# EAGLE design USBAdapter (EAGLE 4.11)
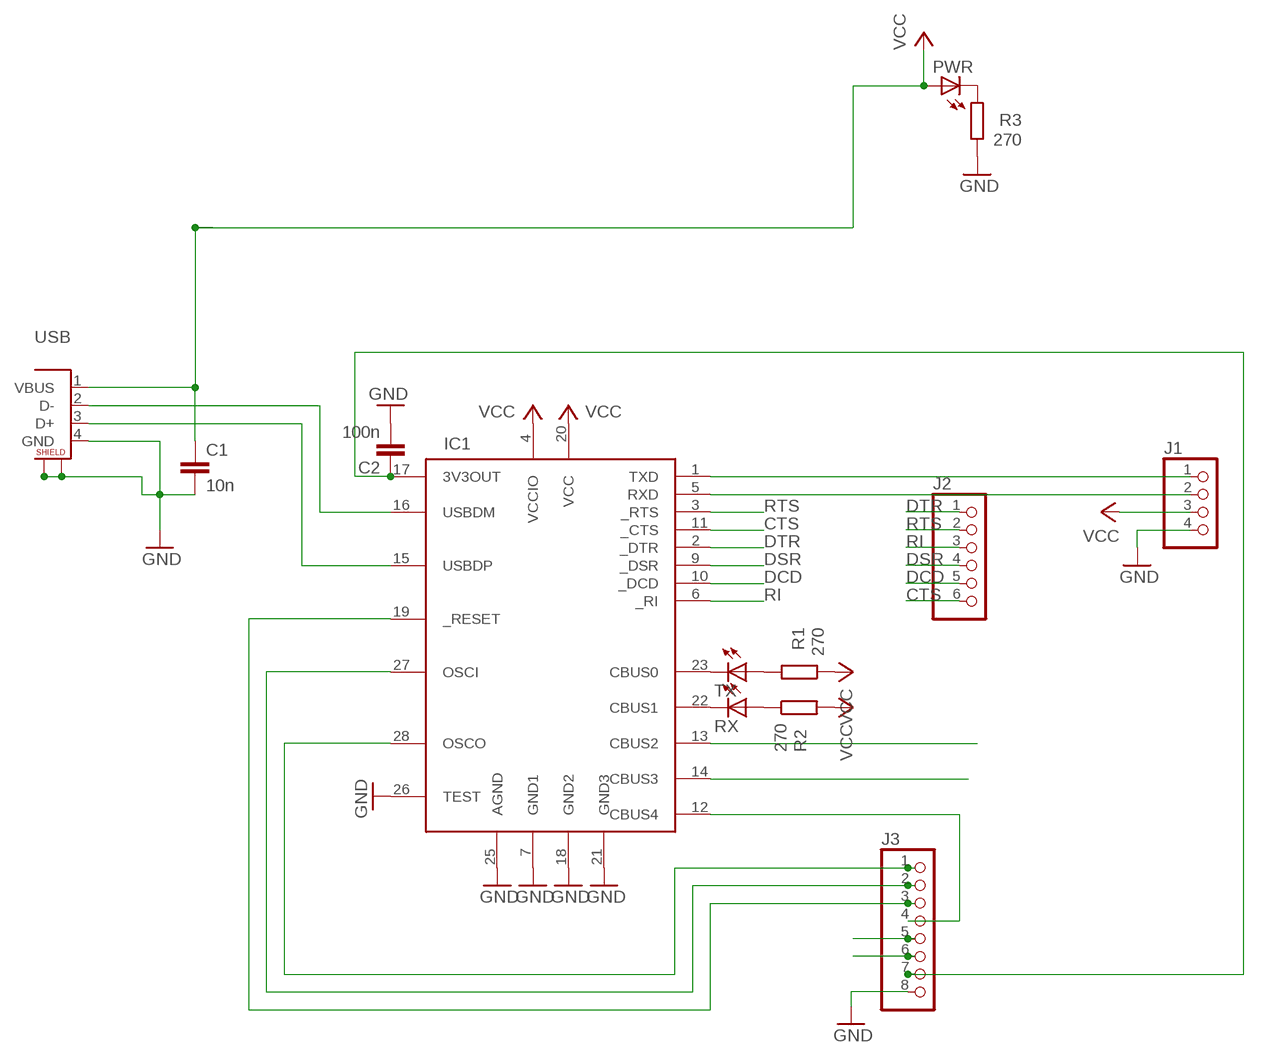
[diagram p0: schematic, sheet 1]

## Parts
C1  10n  C-EUC0805K  [C0805K]
C2  100n  C-EUC0805K  [C0805K]
IC1  FT232RL  [SSOP28DB]
J1  PINHD-1X4  [1X04]
J2  PINHD-1X6  [1X06]
J3  PINHD-1X8  [1X08]
PWR  LEDCHIPLED_0805  [CHIPLED_0805]
R1  270  R-EU_M0805  [M0805]
R2  270  R-EU_M0805  [M0805]
R3  270  R-EU_M0805  [M0805]
RX  LEDCHIPLED_0805  [CHIPLED_0805]
TX  LEDCHIPLED_0805  [CHIPLED_0805]
USB  USB-B  [PN61729]

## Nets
CTS: IC1.11(_CTS) J2.6
DCD: IC1.10(_DCD) J2.5
DSR: IC1.9(_DSR) J2.4
DTR: IC1.2(_DTR) J2.1
GND: C1.2 C2.2 IC1.7(GND1) IC1.18(GND2) IC1.21(GND3) IC1.25(AGND) IC1.26(TEST) J1.4 J3.8 R3.1 USB.4(GND) USB.G1 USB.G2
N$1: IC1.16(USBDM) USB.2(D-)
N$2: IC1.15(USBDP) USB.3(D+)
N$3: C2.1 IC1.17(3V3OUT) J3.7
N$4: IC1.23(CBUS0) TX.C
N$5: IC1.22(CBUS1) RX.C
N$6: R1.2 TX.A
N$7: IC1.1(TXD) J1.1
N$8: R2.1 RX.A
N$9: IC1.5(RXD) J1.2
N$18: IC1.12(CBUS4) J3.4
N$19: IC1.19(_RESET) J3.3
N$20: IC1.27(OSCI) J3.2
N$21: IC1.28(OSCO) J3.1
N$22: IC1.13(CBUS2) J3.5
N$23: IC1.14(CBUS3) J3.6
N$57: PWR.C R3.2
RI: IC1.6(_RI) J2.3
RTS: IC1.3(_RTS) J2.2
VCC: C1.1 IC1.4(VCCIO) IC1.20(VCC) J1.3 PWR.A R1.1 R2.2 USB.1(VBUS)

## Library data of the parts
C1 C2 = rcl:C-EU: CAPACITOR, European symbol
IC1 = ftdichip:FT232RL: USB UART 4th Generation USB UART (USB <-> Serial) Controller
J1 = pinheadModified2:PINHD-1X4: PIN HEADER
J2 = pinheadModified2:PINHD-1X6: PIN HEADER
J3 = pinheadModified2:PINHD-1X8: PIN HEADER
PWR RX TX = led:LED: LED
R1-R3 = rcl:R-EU_: RESISTOR, European symbol
USB = ads4:USB-B: USB Type-B Connector

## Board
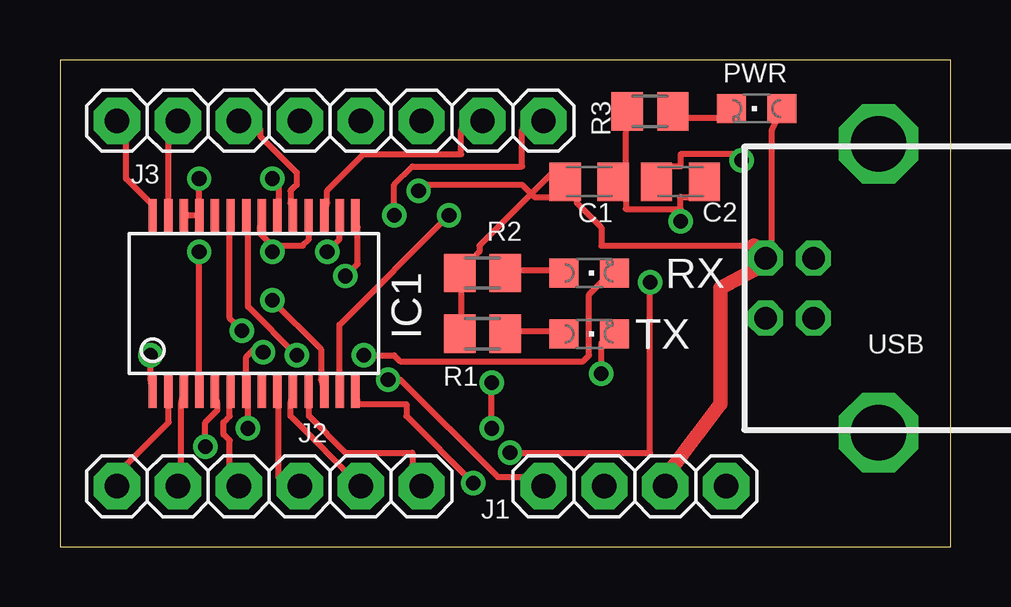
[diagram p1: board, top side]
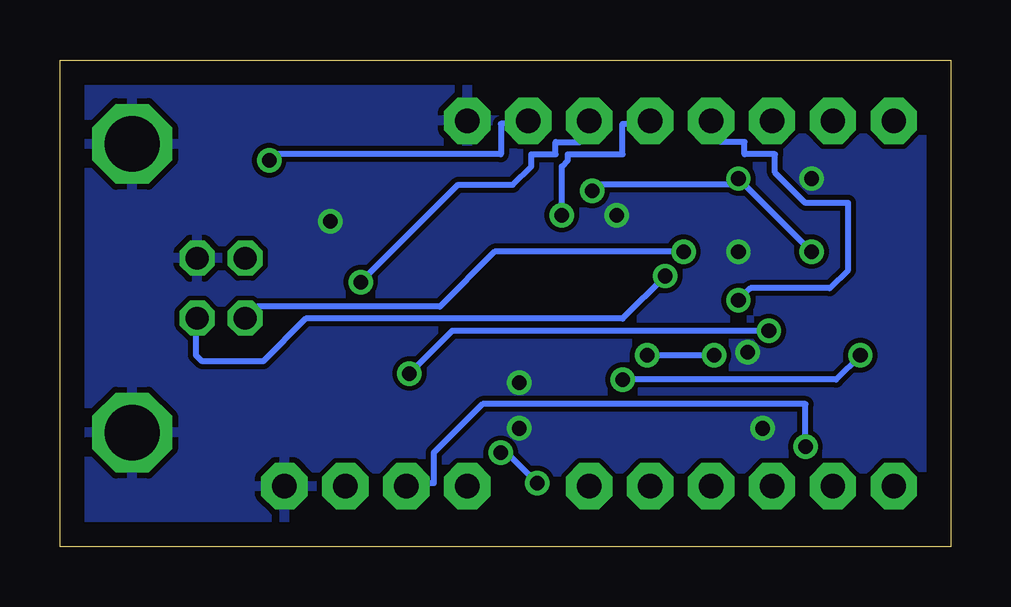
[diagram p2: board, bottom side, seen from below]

Size 37.13 x 20.31 mm. Coordinates in mm from the lower left corner, seen from the top.
Outline: 0,0 37.13,0 37.13,20.31 0,20.31 0,0
Copper layers (1*16): Top 0.035mm / dielectric 1.5mm / Bottom 0.035mm
Design rules "default": minimum track width 10mil, minimum drill 24mil, track to track 8mil, track to pad 8mil, pad to pad 8mil, via to via 8mil, smd to smd 8mil, copper to edge 40mil, drill to drill 8mil, minimum pad ring 10mil, minimum via ring 8mil, stop-mask expansion 4mil, vias tented up to drill 0mil, thermal gap 10mil

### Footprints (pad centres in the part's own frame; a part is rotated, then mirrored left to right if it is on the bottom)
C0805K = smd 1.3 x 1.6: 1 -1,0; 2 1,0
SSOP28DB = smd 0.348 x 1.397: 1 -4.225,-3.656; 2 -3.575,-3.656; 3 -2.925,-3.656; 4 -2.275,-3.656; 5 -1.625,-3.656; 6 -0.975,-3.656; 7 -0.325,-3.656; 8 0.325,-3.656; 9 0.975,-3.656; 10 1.625,-3.656; 11 2.275,-3.656; 12 2.925,-3.656; 13 3.575,-3.656; 14 4.225,-3.656; 15 4.225,3.656; 16 3.575,3.656; 17 2.925,3.656; 18 2.275,3.656; 19 1.625,3.656; 20 0.975,3.656; 21 0.325,3.656; 22 -0.325,3.656; 23 -0.975,3.656; 24 -1.625,3.656; 25 -2.275,3.656; 26 -2.925,3.656; 27 -3.575,3.656; 28 -4.225,3.656
1X04 = drill 1.016 pad 1.93 octagon: 1 -3.81,0; 2 -1.27,0; 3 1.27,0; 4 3.81,0
1X06 = drill 1.016 pad 1.93 octagon: 1 -6.35,0; 2 -3.81,0; 3 -1.27,0; 4 1.27,0; 5 3.81,0; 6 6.35,0
1X08 = drill 1.016 pad 1.93 octagon: 1 -8.89,0; 2 -6.35,0; 3 -3.81,0; 4 -1.27,0; 5 1.27,0; 6 3.81,0; 7 6.35,0; 8 8.89,0
CHIPLED_0805 = smd 1.2 x 1.2: A 0,-1.05; C 0,1.05
M0805 = smd 1.3 x 1.6: 1 -0.95,0; 2 0.95,0
PN61729 = drill 0.95 octagon: 1 1.25,4.71; 2 -1.25,4.71; 3 -1.25,2.71; 4 1.25,2.71 | drill 2.3 octagon: G1 -6.02,0; G2 6.02,0

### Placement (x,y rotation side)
C1  22.06,15.24 0 top
C2  25.87,15.24 0 top
IC1  8.09,10.16 0 top
J1  23.96,2.54 0 top
J2  8.73,2.54 0 top
J3  11.27,17.77 0 top
PWR  29.04,18.28 90 top
R1  17.61,8.89 0 top
R2  17.61,11.43 180 top
R3  24.6,18.16 0 top
RX  22.06,11.43 270 top
TX  22.06,8.89 270 top
USB  34.12,10.79 90 top

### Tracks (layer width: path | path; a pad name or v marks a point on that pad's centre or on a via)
CTS
  Top 0.254: IC1.11 10.38,5.96 10.38,5.46 11.9,3.93 14.69,3.93 14.69,3.42 J2.6
DCD
  Top 0.254: IC1.10 9.61,5.96 9.61,5.46 J2.5
DSR
  Top 0.254: IC1.9 9.11,5.96 9.11,2.92 J2.4
DTR
  Top 0.254: IC1.2 4.53,5.96 4.53,5.2 2.76,3.42 J2.1
GND  (via drill 0.61)
  Top 0.254: 25.87,14.09 25.87,14.6 26.38,14.6 C2.2 | 25.87,14.09 23.58,14.09 23.58,14.6 C1.2 23.58,15.87 23.58,17.14 R3.1 | 8.85,12.57 8.34,13.08 8.34,13.33 IC1.21 | 8.85,12.57 10.12,12.57 10.38,12.82 10.38,13.33 IC1.18 | IC1.26 5.3,13.84 5.8,13.84 IC1.25 5.8,14.35 v5.8,15.36 | v7.84,4.95 7.84,5.96 IC1.7 7.76,7.92 8.09,8.25 8.22,8.12 v8.47,8.12 | v8.85,12.31 8.85,12.57 | 25.87,14.09 v25.87,13.58 | v18,4.95 v18,6.85 | v13.93,13.84 13.93,15.11 14.69,15.87 19.27,15.87 19.27,17.39 J3.8
  pour Bottom: 0.47,19.68 36.66,19.68 36.66,0.63 0.47,0.63
N$1  (via drill 0.61)
  Top 0.254: v11.14,12.31 11.65,12.82 11.65,13.33 IC1.16
  Bottom 0.254: v11.14,12.31 19.01,12.31 21.3,10.03 28.92,10.03 USB.2
N$2  (via drill 0.61)
  Top 0.254: v11.9,11.3 12.41,11.81 12.41,13.33 IC1.15
  Bottom 0.254: v11.9,11.3 13.68,9.52 26.89,9.52 28.66,7.74 31.2,7.74 31.46,8 31.46,9.01 USB.3
N$3  (via drill 0.61)
  Top 0.254: IC1.17 11.14,14.35 11.14,14.85 12.66,16.38 16.73,16.38 16.73,17.39 J3.7 | v28.41,16.12 28.41,16.38 25.87,16.38 25.87,15.87 25.36,15.87 C2.1
  Bottom 0.254: v28.41,16.12 28.16,16.38 18.76,16.38 18.76,17.65 18.5,17.65 J3.7
N$4  (via drill 0.61)
  Top 0.254: v22.57,7.23 22.57,8.5 TX.C | v7.58,9.01 7.07,9.52 7.07,13.33 IC1.23
  Bottom 0.254: v22.57,7.23 20.79,9.01 v7.58,9.01
N$5  (via drill 0.61)
  Top 0.254: v12.66,8 13.93,8 14.19,7.74 21.81,7.74 22.06,8 22.06,10.54 22.57,11.04 RX.C | v9.87,8 7.84,10.03 7.84,13.33 IC1.22
  Bottom 0.254: v9.87,8 v12.66,8
N$6
  Top 0.254: TX.A 20.54,9.01 19.01,9.01 R1.2
N$7  (via drill 0.61)
  Top 0.254: v3.77,8 3.77,6.98 IC1.1 | v13.68,6.98 14.19,6.98 18.25,2.92 19.27,2.92 J1.1
  Bottom 0.254: v3.77,8 4.79,6.98 v13.68,6.98
N$8
  Top 0.254: RX.A 20.54,11.55 19.01,11.55 R2.1
N$9  (via drill 0.61)
  Top 0.254: v6.06,4.19 6.06,5.2 6.57,5.71 6.57,5.96 IC1.5
  Bottom 0.254: v6.06,4.19 6.06,5.96 19.52,5.96 21.55,3.93 21.55,2.66 21.81,2.66 J1.2
N$18  (via drill 0.61)
  Top 0.254: v8.85,10.28 10.88,8.25 10.88,6.98 IC1.12
  Bottom 0.254: v8.85,10.28 8.34,10.79 5.04,10.79 4.28,11.55 4.28,14.35 6.06,14.35 7.33,15.62 7.33,16.38 8.6,16.38 8.6,16.89 9.61,16.89 J3.4
N$19
  Top 0.254: IC1.19 9.61,14.35 9.61,14.85 9.87,15.11 9.87,15.62 8.34,17.14 8.34,17.39 J3.3
N$20
  Top 0.254: IC1.27 4.53,14.35 4.53,16.89 J3.2
N$21
  Top 0.254: IC1.28 3.77,14.35 2.76,15.36 2.76,16.89 J3.1
N$22  (via drill 0.61)
  Top 0.254: v16.22,13.84 11.65,9.27 11.65,6.98 IC1.13
  Bottom 0.254: v16.22,13.84 16.22,15.87 15.96,16.12 15.96,16.38 13.68,16.38 13.68,17.65 13.42,17.65 J3.5
N$23  (via drill 0.61)
  Top 0.254: v17.23,2.66 14.44,5.46 14.44,5.96 12.41,5.96 IC1.14 | v18.76,3.93 24.6,3.93 v24.6,11.04
  Bottom 0.254: v17.23,2.66 18.5,3.93 v18.76,3.93 | v24.6,11.04 20.54,15.11 18.25,15.11 17.49,15.87 17.49,16.38 16.47,16.38 16.47,16.89 15.46,16.89 J3.6
N$57
  Top 0.254: PWR.C 27.65,17.9 26.12,17.9 R3.2
RI
  Top 0.254: IC1.6 7.07,5.96 7.07,5.46 6.82,5.2 6.82,4.69 7.07,4.44 7.07,3.42 J2.3
RTS
  Top 0.254: IC1.3 5.04,5.96 5.04,3.42 J2.2
VCC  (via drill 0.61)
  Top 0.254: PWR.A 29.68,17.39 29.68,12.57 USB.1 | 28.92,12.57 22.57,12.57 22.57,13.33 21.55,14.35 21.55,14.6 C1.1 | R1.1 16.73,9.52 16.73,10.79 R2.2 17.23,12.06 17.49,12.31 17.49,12.57 20.54,15.62 C1.1 | v5.8,12.31 5.8,6.98 IC1.4 | v8.85,15.36 9.11,15.11 9.11,14.35 IC1.20 | v14.95,14.85 14.95,15.11 19.27,15.11 19.77,14.6 20.54,14.6 C1.1
  Top 0.61: J1.3 25.62,3.42 27.52,5.96 27.52,10.79 28.92,11.55 USB.1 28.92,12.57
  Bottom 0.254: v5.8,12.31 v8.85,15.36 9.11,15.11 14.69,15.11 v14.95,14.85

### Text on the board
tDocu: +3.3V | GND | GND | wiring.org.co | Tx | Rx | +5V | GND | USBAdapter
